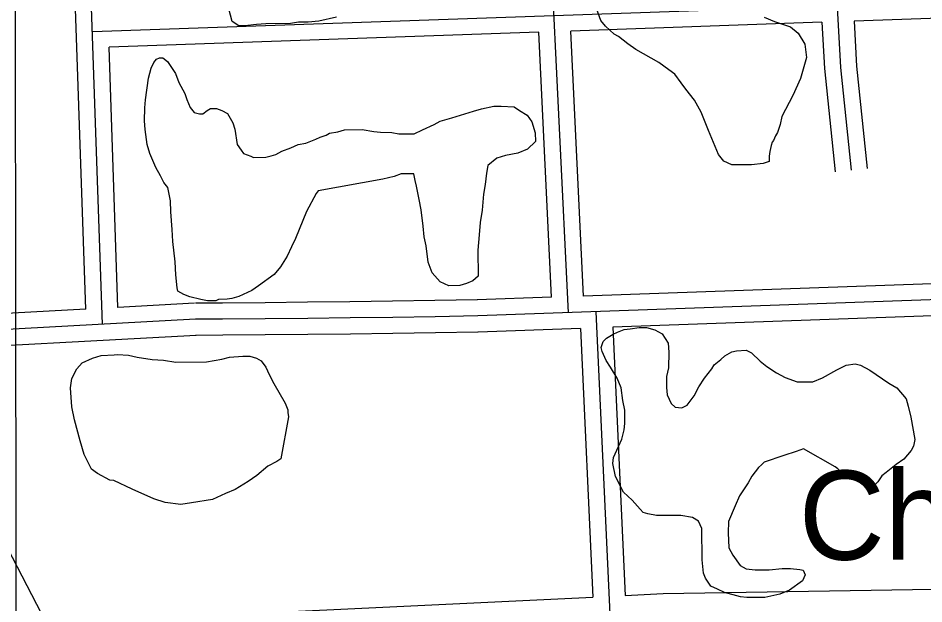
# Model space of a CAD drawing. Extents: x 3313442 to 3351311, y 721974 to 747360.
# Drawn here: x 3328063 to 3328908, y 737395 to 737941 of the extents above; entities that cross this region are included whole.
import ezdxf

# ---------------------------------------------------------------- set-up
doc = ezdxf.new("R2010")
doc.units = 0
for name, color, linetype in [('V-GRID-MAJR', 7, 'Continuous'), ('V-ROAD-CNTR', 7, 'Continuous'), ('V-SITE-OTLN-IDEN', 7, 'Continuous'), ('V-SITE-VEGE', 7, 'Continuous')]:
    doc.layers.add(name, color=color, linetype=linetype)

msp = doc.modelspace()

# ---------------------------------------------------------------- linework, layer by layer
at = {"layer": 'V-GRID-MAJR'}
msp.add_spline([(3328075.07, 727366.28), (3328067.14, 733424.95), (3328059.2, 739486.71), (3328051.27, 745548.49), (3328051.26, 745551.55)], degree=3, dxfattribs=at)
at = {"layer": 'V-ROAD-CNTR'}
for points in [[(3327403.79, 738699.83), (3328760.78, 736081.16)], [(3328812.9, 738203.09), (3328830.15, 737894.9), (3328839.93, 737799.11)], [(3328576.28, 737666.2), (3328551.28, 738182.85)], [(3328126.27, 737669.55), (3328113.35, 738049.05)], [(3328141.76, 737655.37), (3328128.34, 738049.56)], [(3329118.42, 737962.55), (3328132.47, 737928.17)], [(3329100.31, 737946.9), (3328842.77, 737937.93)], [(3328812.78, 737936.88), (3328578.6, 737928.71)], [(3328812.78, 737936.88), (3328815.2, 737893.71), (3328825, 737797.58)], [(3328842.77, 737937.93), (3328845.11, 737896.08), (3328854.85, 737800.63)], [(3328548.61, 737927.67), (3328147.97, 737913.7)], [(3328560.56, 737680.66), (3328548.61, 737927.67)], [(3328590.55, 737681.72), (3328578.6, 737928.71)], [(3328156.23, 737671.17), (3328147.97, 737913.7)], [(3329933.22, 737714.2), (3328491.76, 737663.21)], [(3329055.62, 737698.17), (3328590.55, 737681.72)], [(3329933.75, 737699.21), (3328617.63, 737652.66)], [(3328560.57, 737680.66), (3328491.23, 737678.2)], [(3328227.73, 737675.05), (3328156.23, 737671.17)], [(3328491.49, 737678.21), (3328451.87, 737677.51), (3328412.26, 737676.89), (3328372.64, 737676.36), (3328333.03, 737675.9), (3328293.41, 737675.52), (3328253.8, 737675.22), (3328228.45, 737675.07)], [(3328126.27, 737669.55), (3327949.59, 737659.97)], [(3328601.95, 737667.11), (3328640.3, 736834.6)], [(3328228.54, 737660.07), (3327950.41, 737644.99)], [(3328491.76, 737663.21), (3328452.12, 737662.51), (3328412.47, 737661.9), (3328372.83, 737661.36), (3328333.19, 737660.9), (3328293.54, 737660.52), (3328253.9, 737660.22), (3328228.54, 737660.07)], [(3328492.02, 737648.22), (3328452.36, 737647.52), (3328412.69, 737646.9), (3328373.02, 737646.36), (3328333.35, 737645.9), (3328293.67, 737645.52), (3328254, 737645.22), (3328228.63, 737645.07)], [(3328587.65, 737651.6), (3328492.29, 737648.22)], [(3328587.65, 737651.6), (3328599.18, 737401.21)], [(3328617.63, 737652.66), (3328629.15, 737402.65)], [(3328229.35, 737645.09), (3327951.22, 737630.02)], [(3328629.15, 737402.65), (3328664.77, 737404.36), (3328994.26, 737409.68)], [(3328096.29, 737377.07), (3328599.18, 737401.21)]]:
    msp.add_lwpolyline(points, dxfattribs=at)
at = {"layer": 'V-SITE-VEGE'}
for points in [[(3328360.06, 737941.63), (3328343.58, 737937.83), (3328333.8, 737937.14), (3328324.62, 737937.07), (3328317.3, 737935.78), (3328294.06, 737935.6), (3328285.5, 737934.92), (3328274.51, 737933.6), (3328269, 737933.56), (3328262.85, 737937.79), (3328256.55, 737961.59)], [(3328758.79, 737941.78), (3328768.61, 737937.58), (3328783.32, 737932.8), (3328790.71, 737926.75), (3328796.91, 737916.4), (3328798.23, 737904.18), (3328792.88, 737884.57), (3328785.68, 737868.61), (3328775.44, 737848.96), (3328773.66, 737841.6), (3328771.28, 737834.24), (3328769.46, 737831.17), (3328767.66, 737826.88), (3328766.46, 737825.04), (3328765.26, 737821.96), (3328764.08, 737816.45), (3328763.5, 737812.17), (3328763.54, 737807.28), (3328758.05, 737805.4), (3328747.05, 737804.08), (3328728.71, 737803.94), (3328721.34, 737807.55), (3328716.4, 737813.62), (3328707.04, 737836.18), (3328700.18, 737853.24), (3328693.98, 737864.2), (3328685.94, 737874.53), (3328681.61, 737880.61), (3328675.44, 737888.52), (3328669.9, 737892.75), (3328660.67, 737899.4), (3328639.17, 737911.46), (3328631.79, 737916.91), (3328623.17, 737923.57), (3328618.87, 737925.98), (3328610.86, 737933.25), (3328606.54, 737938.72), (3328601.54, 737952.13)], [(3328509.6, 737810.37), (3328501.09, 737803.57), (3328499.93, 737796.23), (3328498.79, 737785.82), (3328497.03, 737776.63), (3328495.92, 737761.95), (3328494.18, 737750.31), (3328493.05, 737738.69), (3328491.94, 737724.61), (3328492.14, 737700.15), (3328487.28, 737695.83), (3328481.19, 737693.34), (3328475.09, 737691.45), (3328464.69, 737691.37), (3328456.71, 737694.97), (3328449.3, 737703.48), (3328445.56, 737713.23), (3328443.6, 737728.5), (3328441.7, 737737.05), (3328441, 737746.83), (3328439.05, 737762.1), (3328437.14, 737771.87), (3328434.59, 737784.08), (3328433.32, 737789.58), (3328432.05, 737795.68), (3328420.43, 737795.59), (3328413.72, 737793.09), (3328403.35, 737790.56), (3328342.89, 737779.68), (3328341.08, 737777.21), (3328332.04, 737760.63), (3328321.84, 737735.47), (3328318.24, 737727.49), (3328314.02, 737718.9), (3328307.99, 737709.07), (3328301.93, 737701.68), (3328287.34, 737691.17), (3328281.26, 737686.84), (3328269.07, 737681.23), (3328262.36, 737679.35), (3328258.09, 737678.7), (3328250.14, 737678.64), (3328247.7, 737677.39), (3328239.75, 737677.33), (3328233.63, 737678.5), (3328223.21, 737680.87), (3328217.69, 737683.27), (3328212.16, 737686.28), (3328211.52, 737689.33), (3328210.2, 737701.55), (3328209.49, 737713.78), (3328207.5, 737732.72), (3328206.8, 737743.72), (3328205.45, 737760.22), (3328205.36, 737770.62), (3328202.82, 737782.83), (3328199.11, 737787.69), (3328196, 737793.79), (3328191.66, 737801.7), (3328186.06, 737814.5), (3328183.54, 737823.04), (3328181.59, 737837.09), (3328180.92, 737845.03), (3328181.43, 737857.27), (3328181.98, 737864.61), (3328184.88, 737884.82), (3328187.25, 737894.01), (3328189.65, 737899.53), (3328192.07, 737902.61), (3328195.12, 737903.86), (3328198.18, 737903.88), (3328202.49, 737900.25), (3328209.92, 737889.3), (3328213.04, 737880.76), (3328218.63, 737870.41), (3328220.51, 737864.92), (3328223.62, 737857.61), (3328227.33, 737852.74), (3328232.23, 737851.56), (3328235.29, 737851.59), (3328239.55, 737854.68), (3328242.59, 737856.54), (3328248.1, 737856.58), (3328253, 737854.79), (3328258.53, 737851.77), (3328263.49, 737843.25), (3328265.38, 737837.15), (3328267.32, 737823.1), (3328271.03, 737817.63), (3328273.5, 737814.59), (3328280.25, 737812.2), (3328282.71, 737810.99), (3328294.33, 737811.09), (3328299.21, 737812.35), (3328303.48, 737813.61), (3328308.96, 737816.71), (3328317.5, 737819.83), (3328324.2, 737822.94), (3328331.52, 737824.23), (3328340.67, 737827.97), (3328344.94, 737829.84)], [(3328344.94, 737829.84), (3328350.42, 737831.72), (3328353.47, 737833.58), (3328361.41, 737834.87), (3328367.51, 737836.75), (3328384.02, 737836.88), (3328395.04, 737835.13), (3328401.16, 737834.57), (3328411.56, 737834.05), (3328418.3, 737832.88), (3328432.36, 737832.99), (3328440.28, 737836.72), (3328451.25, 737841.7), (3328456.73, 737844.8), (3328467.71, 737847.95), (3328487.84, 737854.23), (3328495.16, 737856.12), (3328506.76, 737858.66), (3328513.49, 737858.71), (3328525.73, 737858.2), (3328530.65, 737854.57), (3328538.02, 737850.35), (3328542.35, 737844.27), (3328545.49, 737833.9), (3328545.56, 737825.95), (3328538.28, 737818.55), (3328529.13, 737814.81), (3328517.53, 737812.88), (3328509.6, 737810.37)], [(3328628.91, 737575.27), (3328627, 737584.43), (3328625.68, 737596.04), (3328621.94, 737605.18), (3328615.74, 737615.53), (3328611.41, 737621.61), (3328607.67, 737630.14), (3328607.03, 737633.8), (3328608.82, 737639.32), (3328611.85, 737642.4), (3328617.94, 737646.12), (3328622.21, 737647.99), (3328628.3, 737650.49), (3328633.8, 737651.14), (3328642.35, 737652.43), (3328649.08, 737652.49), (3328657.05, 737650.11), (3328663.81, 737646.49), (3328669.38, 737637.97), (3328670.06, 737629.42), (3328669.56, 737614.74), (3328667.79, 737606.77), (3328667.88, 737596.38), (3328668.54, 737589.66), (3328672.28, 737581.73)], [(3328672.28, 737581.73), (3328675.97, 737578.1), (3328682.09, 737577.53), (3328686.97, 737580.02), (3328693.62, 737588.63), (3328697.84, 737597.23), (3328703.28, 737605.22), (3328709.93, 737613.84), (3328712.35, 737617.53), (3328718.43, 737622.47), (3328722.07, 737626.17), (3328728.76, 737629.89), (3328733.04, 737630.54), (3328742.21, 737631.22), (3328747.12, 737628.81), (3328755.13, 737620.93), (3328761.28, 737616.09), (3328770.51, 737610.05), (3328778.49, 737605.83), (3328789.53, 737601.64), (3328804.21, 737601.75), (3328813.35, 737605.5), (3328826.75, 737612.94), (3328835.27, 737617.29), (3328843.83, 737618.59), (3328848.73, 737617.4), (3328857.33, 737612.58), (3328875.16, 737600.49), (3328882.53, 737596.27), (3328891.18, 737585.94), (3328893.07, 737579.23), (3328895.6, 737568.85), (3328899.43, 737548.09), (3328898.26, 737541.97), (3328895.85, 737537.67), (3328889.18, 737529.66), (3328881.88, 737524.71), (3328872.77, 737517.3), (3328868.52, 737514.21), (3328864.89, 737508.68), (3328863.07, 737506.82), (3328858.19, 737505.56), (3328852.69, 737505.52), (3328844.08, 737510.34), (3328840.4, 737512.15), (3328829.96, 737518.18), (3328827.49, 737520.6), (3328825.03, 737522.42), (3328795.54, 737539.31), (3328788.83, 737536.8), (3328777.24, 737533.04), (3328758.95, 737526.78), (3328756.52, 737524.31), (3328753.48, 737521.84), (3328747.43, 737513.85), (3328743.81, 737507.7), (3328735.96, 737495.41), (3328731.75, 737486.2), (3328725.76, 737471.47), (3328725.23, 737461.08), (3328725.95, 737447.01), (3328729.68, 737440.32), (3328736.48, 737430.59), (3328742.01, 737427.57), (3328750.58, 737426.42), (3328763.42, 737426.52), (3328775.64, 737427.84), (3328783.59, 737427.91), (3328792.16, 737426.75), (3328795.23, 737426.17), (3328797.1, 737421.9), (3328794.69, 737416.38), (3328782.53, 737407.72), (3328773.39, 737403.97), (3328759.35, 737400.81), (3328742.84, 737400.67), (3328736.72, 737401.23), (3328722, 737405.4), (3328715.25, 737408.4), (3328709.12, 737411.41), (3328704.17, 737418.71), (3328702.29, 737423.58), (3328700.97, 737435.81), (3328700.73, 737465.16), (3328697.62, 737471.86), (3328692.09, 737475.48), (3328681.07, 737477.23), (3328658.44, 737477.05), (3328650.48, 737478.82), (3328646.18, 737480.01), (3328643.1, 737483.04), (3328635.7, 737491.54), (3328627.69, 737498.82), (3328620.23, 737513.43), (3328617.69, 737525.64), (3328618.25, 737531.15), (3328623.06, 737541.59), (3328626.07, 737548.34), (3328628.44, 737556.92), (3328629, 737563.04), (3328628.91, 737575.27)]]:
    msp.add_lwpolyline(points, dxfattribs=at)
msp.add_lwpolyline([(3328308.21, 737529.88), (3328304.56, 737527.41), (3328296.03, 737523.06), (3328285.7, 737514.41), (3328277.8, 737508.84), (3328265.63, 737501.41), (3328256.48, 737497.67), (3328244.3, 737492.07), (3328224.75, 737488.85), (3328214.98, 737487.55), (3328200.29, 737489.27), (3328189.86, 737492.85), (3328169.61, 737501.86), (3328152.42, 737509.67), (3328148.75, 737510.26), (3328137.08, 737516.28), (3328131.54, 737520.51), (3328124.71, 737533.91), (3328120.94, 737546.72), (3328115.89, 737566.25), (3328113.34, 737578.46), (3328111.98, 737596.19), (3328113.13, 737604.76), (3328117.95, 737613.97), (3328122.79, 737619.52), (3328132.55, 737623.88), (3328140.48, 737626.38), (3328152.7, 737627.09), (3328155.76, 737627.12), (3328166.16, 737626.59), (3328174.12, 737624.82), (3328188.21, 737622.49), (3328198.61, 737621.96), (3328210.25, 737620.22), (3328238.98, 737620.45), (3328253.03, 737623.01), (3328260.35, 737624.9), (3328272.58, 737625.61), (3328279.31, 737625.67), (3328285.44, 737623.88), (3328289.74, 737621.47), (3328294.06, 737615.39), (3328297.18, 737608.69), (3328301.53, 737600.16), (3328312.07, 737581.9), (3328314.57, 737575.8), (3328314.58, 737573.35), (3328315.23, 737569.08)], close=True, dxfattribs=at)

# ---------------------------------------------------------------- texts
at = {"layer": 'V-SITE-OTLN-IDEN'}
msp.add_text('Ch.', height=83, dxfattribs=at).set_placement((3328791.16, 737435.96))

doc.saveas('drawing.dxf')
